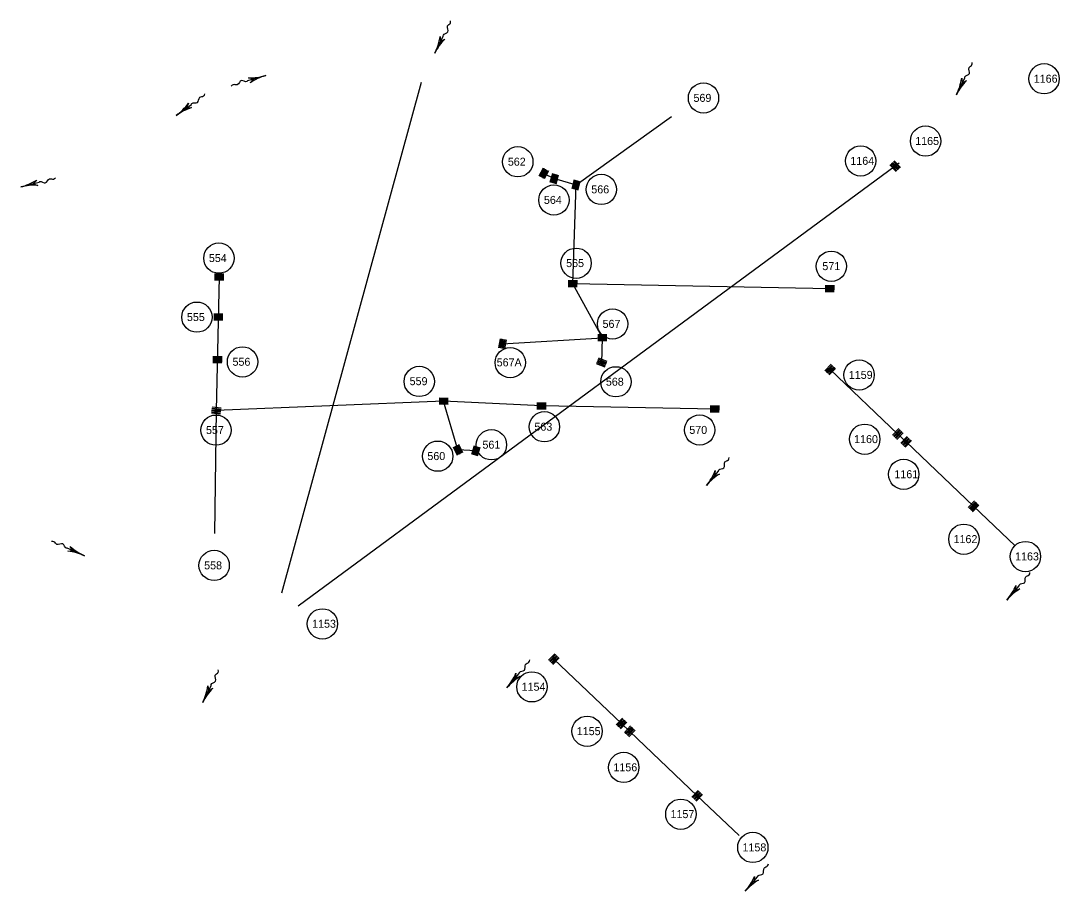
# Model space of a CAD drawing. Extents: x 594534 to 598564, y 225861 to 236229.
# Drawn here: x 596065 to 596844, y 230686 to 231339 of the extents above; entities that cross this region are included whole.
import ezdxf

# ---------------------------------------------------------------- set-up
doc = ezdxf.new("R2010")
doc.units = 0
for name, color, linetype in [('P_AREA', 7, 'Continuous'), ('P_DRN_Flow', 7, 'Continuous'), ('P_DRN_Inlet', 7, 'Continuous'), ('P_DRN_Pipes', 7, 'Continuous'), ('P_DRN_SS_UG', 7, 'Continuous'), ('P_DRN_Text', 7, 'Continuous')]:
    doc.layers.add(name, color=color, linetype=linetype)

msp = doc.modelspace()

# ---------------------------------------------------------------- linework, layer by layer
at = {"layer": 'P_AREA'}
msp.add_line((596212.74, 231083.95), (596212.76, 231084.95), dxfattribs=at)
at = {"layer": 'P_DRN_Flow'}
for p, q in [((596375.65, 231314.78), (596382.04, 231327.39)), ((596249, 231297.91), (596235.45, 231293.92)), ((596249, 231297.91), (596235.45, 231293.92)), ((596766.56, 231283.57), (596772.94, 231296.17)), ((596181.86, 231267.94), (596193.27, 231276.28)), ((596181.86, 231267.94), (596193.27, 231276.28)), ((596065.42, 231214.43), (596079.12, 231217.86)), ((596579.21, 230990.57), (596588.28, 231001.4)), ((596113.24, 230937.89), (596100.31, 230943.58)), ((596113.24, 230937.89), (596100.31, 230943.58)), ((596804.34, 230904.63), (596813.56, 230915.33)), ((596429.76, 230838.79), (596438.83, 230849.62)), ((596201.78, 230827.89), (596208.04, 230840.55)), ((596608.39, 230686.29), (596617.61, 230696.99))]:
    msp.add_line(p, q, dxfattribs=at)
for points in [[(596379.65, 231327.1), (596379.99, 231323.34), (596383.22, 231325.3)], [(596237.3, 231292.37), (596239.8, 231295.19), (596236.16, 231296.21)], [(596237.3, 231292.37), (596239.8, 231295.19), (596236.16, 231296.21)], [(596770.55, 231295.89), (596770.89, 231292.13), (596774.12, 231294.09)], [(596191.01, 231277.11), (596189.61, 231273.6), (596193.37, 231273.88)], [(596191.01, 231277.11), (596189.61, 231273.6), (596193.37, 231273.88)], [(596077.35, 231219.48), (596074.73, 231216.77), (596078.32, 231215.6)], [(596585.89, 231001.67), (596585.37, 230997.93), (596588.96, 230999.1)], [(596100.72, 230941.21), (596104.46, 230941.75), (596102.33, 230944.88)], [(596100.72, 230941.21), (596104.46, 230941.75), (596102.33, 230944.88)], [(596811.17, 230915.63), (596810.6, 230911.9), (596814.21, 230913.02)], [(596436.44, 230849.88), (596435.92, 230846.15), (596439.51, 230847.32)], [(596205.65, 230840.24), (596206.03, 230836.49), (596209.24, 230838.47)], [(596615.22, 230697.29), (596614.65, 230693.56), (596618.26, 230694.68)]]:
    msp.add_lwpolyline(points, dxfattribs=at)
for centre, start, end in [((596338.22, 231333.75), 333.12797, 350.89029), ((596413.08, 231295.82), 135.36565, 153.12797), ((596237.14, 231338.15), 268.66582, 286.42814), ((596237.14, 231338.15), 268.66582, 286.42814), ((596260.87, 231257.67), 106.42814, 124.19046), ((596260.87, 231257.67), 106.42814, 124.19046), ((596729.13, 231302.54), 333.12797, 350.89029), ((596803.98, 231264.61), 135.36565, 153.12797), ((596157.11, 231301.83), 306.14258, 323.9049), ((596157.11, 231301.83), 306.14258, 323.9049), ((596206.61, 231234.06), 108.38026, 126.14258), ((596206.61, 231234.06), 108.38026, 126.14258), ((596055.22, 231255.13), 284.06213, 301.82445), ((596075.61, 231173.73), 86.29981, 104.06213), ((596547.05, 231017.52), 320.04245, 337.80477), ((596611.37, 230963.63), 122.28013, 140.04245), ((596130.16, 230976.28), 228.45383, 246.21615), ((596130.16, 230976.28), 228.45383, 246.21615), ((596096.32, 230899.49), 66.21615, 83.97847), ((596096.32, 230899.49), 66.21615, 83.97847), ((596772.55, 230932), 319.27709, 337.03941), ((596836.14, 230877.25), 121.51478, 139.27709), ((596397.6, 230865.73), 320.04245, 337.80477), ((596461.92, 230811.84), 122.28013, 140.04245), ((596164.17, 230846.48), 333.6884, 351.45072), ((596239.39, 230809.29), 135.92608, 153.6884), ((596576.6, 230713.66), 319.27709, 337.03941), ((596640.19, 230658.91), 121.51478, 139.27709)]:
    msp.add_arc(centre, 41.96, start, end, dxfattribs=at)
for points in [[(596382.04, 231327.39), (596382.11, 231328.23), (596385.42, 231330.6), (596385.24, 231335.09), (596387.35, 231337.19), (596387.57, 231339.01)], [(596772.94, 231296.17), (596773.02, 231297.02), (596776.33, 231299.39), (596776.14, 231303.88), (596778.26, 231305.97), (596778.48, 231307.8)], [(596235.45, 231293.92), (596234.79, 231293.39), (596230.79, 231294.18), (596227.65, 231290.96), (596224.67, 231291.06), (596223.19, 231289.97)], [(596235.45, 231293.92), (596234.79, 231293.39), (596230.79, 231294.18), (596227.65, 231290.96), (596224.67, 231291.06), (596223.19, 231289.97)], [(596193.27, 231276.28), (596193.72, 231276.99), (596197.74, 231277.6), (596199.62, 231281.69), (596202.45, 231282.6), (596203.48, 231284.12)], [(596193.27, 231276.28), (596193.72, 231276.99), (596197.74, 231277.6), (596199.62, 231281.69), (596202.45, 231282.6), (596203.48, 231284.12)], [(596079.12, 231217.86), (596079.81, 231218.36), (596083.77, 231217.41), (596087.04, 231220.5), (596090.01, 231220.27), (596091.53, 231221.3)], [(596588.28, 231001.4), (596588.55, 231002.21), (596592.31, 231003.77), (596593.14, 231008.18), (596595.68, 231009.75), (596596.31, 231011.47)], [(596100.31, 230943.58), (596099.47, 230943.61), (596096.92, 230946.79), (596092.45, 230946.36), (596090.24, 230948.37), (596088.41, 230948.49)], [(596100.31, 230943.58), (596099.47, 230943.61), (596096.92, 230946.79), (596092.45, 230946.36), (596090.24, 230948.37), (596088.41, 230948.49)], [(596813.56, 230915.33), (596813.84, 230916.13), (596817.62, 230917.64), (596818.51, 230922.05), (596821.07, 230923.58), (596821.72, 230925.29)], [(596438.83, 230849.62), (596439.09, 230850.42), (596442.86, 230851.98), (596443.69, 230856.4), (596446.23, 230857.96), (596446.86, 230859.69)], [(596208.04, 230840.55), (596208.11, 230841.39), (596211.39, 230843.79), (596211.16, 230848.29), (596213.26, 230850.4), (596213.46, 230852.23)], [(596617.61, 230696.99), (596617.89, 230697.79), (596621.67, 230699.3), (596622.56, 230703.71), (596625.12, 230705.24), (596625.77, 230706.95)]]:
    msp.add_spline(points, degree=3, dxfattribs=at)
at = {"layer": 'P_DRN_Inlet'}
for p, q in [((596722.71, 231227.14), (596718.02, 231232.17)), ((596723.37, 231227.76), (596718.68, 231232.78)), ((596724.03, 231228.37), (596719.33, 231233.4)), ((596724.69, 231228.99), (596719.99, 231234.01)), ((596456.84, 231228.55), (596453.6, 231222.49)), ((596457.64, 231228.13), (596454.39, 231222.06)), ((596458.43, 231227.7), (596455.19, 231221.64)), ((596459.22, 231227.28), (596455.98, 231221.21)), ((596460.02, 231226.85), (596456.77, 231220.79)), ((596460.81, 231226.43), (596457.57, 231220.36)), ((596462.25, 231218), (596464.09, 231224.63)), ((596463.12, 231217.76), (596464.96, 231224.38)), ((596721.4, 231225.91), (596716.7, 231230.94)), ((596722.06, 231226.53), (596717.36, 231231.55)), ((596463.98, 231217.52), (596465.83, 231224.14)), ((596464.85, 231217.28), (596466.69, 231223.9)), ((596465.72, 231217.04), (596467.56, 231223.66)), ((596466.59, 231216.8), (596468.43, 231223.42)), ((596478.58, 231213.26), (596480.42, 231219.89)), ((596479.44, 231213.02), (596481.28, 231219.65)), ((596480.31, 231212.78), (596482.15, 231219.4)), ((596481.18, 231212.54), (596483.02, 231219.16)), ((596482.04, 231212.3), (596483.89, 231218.92)), ((596482.91, 231212.06), (596484.75, 231218.68)), ((596210.66, 231146.53), (596217.53, 231146.44)), ((596210.67, 231147.43), (596217.55, 231147.34)), ((596210.68, 231148.33), (596217.56, 231148.24)), ((596210.69, 231149.23), (596217.57, 231149.14)), ((596210.64, 231144.73), (596217.51, 231144.64)), ((596210.65, 231145.63), (596217.52, 231145.54)), ((596482.5, 231140.4), (596475.62, 231140.45)), ((596482.49, 231139.5), (596475.62, 231139.55)), ((596482.5, 231141.3), (596475.63, 231141.35)), ((596482.52, 231143.1), (596475.64, 231143.15)), ((596482.51, 231142.2), (596475.64, 231142.25)), ((596482.52, 231144), (596475.65, 231144.05)), ((596675.12, 231139.36), (596668.24, 231139.4)), ((596675.13, 231140.26), (596668.25, 231140.3)), ((596675.09, 231135.76), (596668.22, 231135.8)), ((596675.11, 231137.56), (596668.23, 231137.6)), ((596675.1, 231136.66), (596668.23, 231136.7)), ((596675.11, 231138.46), (596668.24, 231138.5)), ((596210.02, 231115.63), (596216.89, 231115.54)), ((596210.03, 231116.53), (596216.91, 231116.44)), ((596210.04, 231117.43), (596216.92, 231117.34)), ((596210.05, 231118.33), (596216.93, 231118.24)), ((596210.07, 231119.23), (596216.94, 231119.14)), ((596210.01, 231114.73), (596216.88, 231114.64)), ((596424.68, 231100.57), (596423.49, 231093.8)), ((596425.57, 231100.41), (596424.37, 231093.64)), ((596426.45, 231100.26), (596425.26, 231093.49)), ((596427.34, 231100.1), (596426.15, 231093.33)), ((596428.23, 231099.95), (596427.03, 231093.17)), ((596504.71, 231103.58), (596497.83, 231103.58)), ((596504.71, 231102.68), (596497.83, 231102.68)), ((596504.71, 231101.78), (596497.83, 231101.78)), ((596504.71, 231100.88), (596497.83, 231100.88)), ((596504.71, 231099.98), (596497.83, 231099.98)), ((596429.11, 231099.79), (596427.92, 231093.02)), ((596504.71, 231099.08), (596497.83, 231099.08)), ((596209.36, 231084.54), (596216.24, 231084.45)), ((596209.37, 231085.44), (596216.25, 231085.35)), ((596209.39, 231086.34), (596216.26, 231086.25)), ((596209.4, 231087.24), (596216.27, 231087.15)), ((596504.26, 231081.76), (596497.89, 231084.34)), ((596504.6, 231082.6), (596498.22, 231085.17)), ((596504.94, 231083.43), (596498.56, 231086)), ((596209.34, 231082.74), (596216.21, 231082.65)), ((596209.35, 231083.64), (596216.23, 231083.55)), ((596503.25, 231079.26), (596496.88, 231081.83)), ((596503.59, 231080.09), (596497.21, 231082.67)), ((596503.93, 231080.93), (596497.55, 231083.5)), ((596668.02, 231076.52), (596672.79, 231081.47)), ((596668.67, 231075.9), (596673.44, 231080.85)), ((596669.32, 231075.27), (596674.09, 231080.22)), ((596669.97, 231074.65), (596674.74, 231079.6)), ((596670.62, 231074.02), (596675.39, 231078.97)), ((596671.27, 231073.4), (596676.03, 231078.35)), ((596385.75, 231053.17), (596378.88, 231053.22)), ((596385.77, 231054.97), (596378.89, 231055.02)), ((596385.76, 231054.07), (596378.89, 231054.12)), ((596385.77, 231055.87), (596378.9, 231055.92)), ((596208.37, 231045.84), (596215.2, 231045.07)), ((596208.47, 231046.74), (596215.31, 231045.96)), ((596208.58, 231047.63), (596215.41, 231046.86)), ((596208.68, 231048.53), (596215.51, 231047.75)), ((596208.78, 231049.42), (596215.61, 231048.65)), ((596385.75, 231052.27), (596378.87, 231052.32)), ((596385.74, 231051.37), (596378.87, 231051.42)), ((596452.21, 231052.46), (596459.08, 231052.46)), ((596452.21, 231051.56), (596459.08, 231051.56)), ((596452.21, 231050.66), (596459.08, 231050.66)), ((596452.21, 231049.76), (596459.08, 231049.76)), ((596452.21, 231048.86), (596459.08, 231048.86)), ((596452.21, 231047.96), (596459.08, 231047.96)), ((596588.91, 231045.41), (596582.04, 231045.46)), ((596588.93, 231047.21), (596582.05, 231047.26)), ((596588.92, 231046.31), (596582.05, 231046.36)), ((596588.94, 231049.01), (596582.06, 231049.06)), ((596588.93, 231048.11), (596582.06, 231048.16)), ((596588.95, 231049.91), (596582.07, 231049.96)), ((596208.27, 231044.95), (596215.1, 231044.18)), ((596718.68, 231028.18), (596723.42, 231033.16)), ((596719.33, 231027.56), (596724.07, 231032.54)), ((596719.98, 231026.94), (596724.73, 231031.92)), ((596720.63, 231026.32), (596725.38, 231031.3)), ((596721.28, 231025.7), (596726.03, 231030.67)), ((596721.94, 231025.08), (596726.68, 231030.05)), ((596724.83, 231022.32), (596729.57, 231027.29)), ((596725.48, 231021.69), (596730.22, 231026.67)), ((596726.13, 231021.07), (596730.88, 231026.05)), ((596726.78, 231020.45), (596731.53, 231025.43)), ((596727.44, 231019.83), (596732.18, 231024.81)), ((596728.09, 231019.21), (596732.83, 231024.19)), ((596389.42, 231019.45), (596392.5, 231013.31)), ((596390.22, 231019.86), (596393.3, 231013.71)), ((596391.03, 231020.26), (596394.11, 231014.11)), ((596391.83, 231020.66), (596394.91, 231014.51)), ((596392.64, 231021.07), (596395.71, 231014.92)), ((596393.44, 231021.47), (596396.52, 231015.32)), ((596403.35, 231013.96), (596405.34, 231020.54)), ((596404.21, 231013.7), (596406.2, 231020.28)), ((596405.07, 231013.44), (596407.06, 231020.02)), ((596405.94, 231013.18), (596407.92, 231019.76)), ((596406.8, 231012.92), (596408.79, 231019.5)), ((596407.66, 231012.66), (596409.65, 231019.24)), ((596775.48, 230974), (596780.22, 230978.97)), ((596776.13, 230973.38), (596780.87, 230978.35)), ((596776.78, 230972.76), (596781.53, 230977.73)), ((596777.43, 230972.14), (596782.18, 230977.11)), ((596778.09, 230971.51), (596782.83, 230976.49)), ((596778.74, 230970.89), (596783.48, 230975.87)), ((596460.95, 230859.45), (596465.72, 230864.4)), ((596461.6, 230858.82), (596466.37, 230863.78)), ((596462.25, 230858.2), (596467.02, 230863.15)), ((596462.9, 230857.57), (596467.66, 230862.53)), ((596463.54, 230856.95), (596468.31, 230861.9)), ((596464.19, 230856.33), (596468.96, 230861.28)), ((596511.61, 230811.08), (596516.32, 230816.09)), ((596512.27, 230810.46), (596516.97, 230815.48)), ((596512.92, 230809.85), (596517.63, 230814.86)), ((596513.58, 230809.23), (596518.29, 230814.24)), ((596514.24, 230808.62), (596518.94, 230813.63)), ((596514.89, 230808), (596519.6, 230813.01)), ((596517.76, 230805.21), (596522.47, 230810.22)), ((596518.42, 230804.6), (596523.13, 230809.61)), ((596519.07, 230803.98), (596523.78, 230808.99)), ((596519.73, 230803.36), (596524.44, 230808.38)), ((596520.39, 230802.75), (596525.09, 230807.76)), ((596521.04, 230802.13), (596525.75, 230807.14)), ((596568.41, 230756.93), (596573.15, 230761.9)), ((596569.06, 230756.3), (596573.8, 230761.28)), ((596569.71, 230755.68), (596574.45, 230760.66)), ((596570.36, 230755.06), (596575.1, 230760.04)), ((596571.01, 230754.44), (596575.76, 230759.42)), ((596571.66, 230753.82), (596576.41, 230758.8))]:
    msp.add_line(p, q, dxfattribs=at)
for points in [[(596456.79, 231225.81), (596455.85, 231224.05), (596457.62, 231223.1), (596458.56, 231224.87)], [(596722.11, 231229.92), (596720.74, 231231.38), (596719.28, 231230.01), (596720.65, 231228.55)], [(596466.03, 231219.48), (596466.57, 231221.41), (596464.64, 231221.94), (596464.11, 231220.02)], [(596482.36, 231214.74), (596482.9, 231216.67), (596480.97, 231217.2), (596480.43, 231215.28)], [(596213.09, 231145.94), (596215.09, 231145.92), (596215.11, 231147.92), (596213.11, 231147.94)], [(596480.08, 231142.77), (596478.08, 231142.78), (596478.06, 231140.78), (596480.06, 231140.77)], [(596672.68, 231139.02), (596670.68, 231139.04), (596670.67, 231137.04), (596672.67, 231137.02)], [(596212.46, 231115.95), (596214.46, 231115.92), (596214.49, 231117.92), (596212.49, 231117.95)], [(596502.27, 231102.33), (596500.27, 231102.33), (596500.27, 231100.33), (596502.27, 231100.33)], [(596425.49, 231097.95), (596425.14, 231095.98), (596427.11, 231095.64), (596427.46, 231097.61)], [(596211.79, 231083.96), (596213.79, 231083.93), (596213.82, 231085.93), (596211.82, 231085.96)], [(596502.21, 231083.18), (596500.35, 231083.93), (596499.6, 231082.08), (596501.46, 231081.33)], [(596672.06, 231076.02), (596673.44, 231077.46), (596672, 231078.85), (596670.62, 231077.41)], [(596383.33, 231054.63), (596381.33, 231054.65), (596381.31, 231052.65), (596383.31, 231052.63)], [(596210.83, 231045.92), (596212.82, 231045.69), (596213.05, 231047.68), (596211.06, 231047.9)], [(596454.65, 231049.21), (596456.65, 231049.21), (596456.65, 231051.21), (596454.65, 231051.21)], [(596586.5, 231048.68), (596584.5, 231048.7), (596584.49, 231046.7), (596586.49, 231046.68)], [(596722.71, 231027.7), (596724.09, 231029.15), (596722.65, 231030.53), (596721.27, 231029.08)], [(596728.86, 231021.84), (596730.24, 231023.28), (596728.8, 231024.66), (596727.42, 231023.22)], [(596391.63, 231017.83), (596392.52, 231016.05), (596394.31, 231016.94), (596393.42, 231018.73)], [(596407.17, 231015.35), (596407.75, 231017.27), (596405.83, 231017.85), (596405.25, 231015.93)], [(596779.51, 230973.52), (596780.89, 230974.97), (596779.45, 230976.35), (596778.07, 230974.9)], [(596464.98, 230858.95), (596466.37, 230860.39), (596464.93, 230861.78), (596463.54, 230860.34)], [(596515.65, 230810.63), (596517.02, 230812.09), (596515.56, 230813.46), (596514.19, 230812)], [(596521.8, 230804.77), (596523.17, 230806.22), (596521.71, 230807.59), (596520.34, 230806.13)], [(596572.44, 230756.45), (596573.82, 230757.9), (596572.37, 230759.28), (596570.99, 230757.83)]]:
    msp.add_lwpolyline(points, close=True, dxfattribs=at)
at = {"layer": 'P_DRN_Pipes'}
msp.add_line((596365.41, 231292.62), (596260.82, 230909.73), dxfattribs=at)
at = {"layer": 'P_DRN_SS_UG'}
for p, q in [((596481.66, 231215.97), (596553.05, 231267.32)), ((596723.67, 231232.21), (596720.69, 231229.96)), ((596720.69, 231229.96), (596273.27, 230900.09)), ((596457.21, 231224.46), (596465.34, 231220.71)), ((596465.34, 231220.71), (596481.66, 231215.97)), ((596479.07, 231141.78), (596481.66, 231215.97)), ((596214.1, 231146.93), (596211.94, 231046.81)), ((596501.27, 231101.33), (596479.07, 231141.78)), ((596671.67, 231138.03), (596479.07, 231141.78)), ((596426.3, 231096.79), (596501.27, 231101.33)), ((596500.91, 231082.63), (596501.27, 231101.33)), ((596672.03, 231077.44), (596722.68, 231029.12)), ((596382.32, 231053.64), (596211.94, 231046.8)), ((596455.65, 231050.21), (596382.32, 231053.64)), ((596392.97, 231017.39), (596382.32, 231053.64)), ((596211.94, 231046.81), (596210.65, 230954.48)), ((596585.49, 231047.69), (596455.65, 231050.21)), ((596722.68, 231029.12), (596728.83, 231023.25)), ((596728.83, 231023.25), (596779.48, 230974.93)), ((596406.5, 231016.6), (596392.97, 231017.39)), ((596779.48, 230974.93), (596810.5, 230945.35)), ((596464.96, 230860.36), (596515.61, 230812.05)), ((596515.61, 230812.05), (596521.76, 230806.18)), ((596521.76, 230806.18), (596572.41, 230757.86)), ((596572.41, 230757.86), (596603.66, 230728.05))]:
    msp.add_line(p, q, dxfattribs=at)
at = {"layer": 'P_DRN_Text'}
for centre in [(596832.28, 231295.48), (596577.05, 231281.11), (596743.46, 231248.78), (596437.91, 231233.25), (596694.84, 231233.89), (596500.48, 231212.51), (596464.96, 231204.59), (596213.88, 231161.01), (596481.61, 231157.22), (596672.86, 231154.94), (596197.43, 231116.76), (596508.92, 231111.63), (596231.59, 231083.22), (596432.24, 231082.64), (596693.68, 231073.39), (596364.04, 231068.53), (596511.39, 231068.27), (596457.84, 231034.54), (596211.74, 231032.03), (596574.18, 231032.14), (596418.14, 231021.05), (596697.93, 231025.23), (596377.89, 231012.52), (596727.09, 230998.91), (596772.19, 230950.25), (596818.32, 230937.27), (596210.34, 230930.59), (596291.5, 230886.78), (596448.48, 230839.55), (596489.84, 230806.25), (596517.28, 230779.14), (596560.08, 230744.04), (596614.02, 230719.1)]:
    msp.add_circle(centre, 11.36, dxfattribs=at)

# ---------------------------------------------------------------- texts
for s, p in [('1166', (596824.55, 231292.56)), ('569', (596569.56, 231278.19)), ('1165', (596735.72, 231245.86)), ('562', (596430.42, 231230.33)), ('1164', (596687.11, 231230.97)), ('566', (596492.98, 231209.59)), ('564', (596457.47, 231201.67)), ('554', (596206.38, 231158.09)), ('565', (596474.12, 231154.3)), ('571', (596666.12, 231152.02)), ('555', (596189.93, 231113.84)), ('567', (596501.42, 231108.71)), ('556', (596224.09, 231080.3)), ('567A', (596422.08, 231079.86)), ('1159', (596685.94, 231070.47)), ('559', (596356.83, 231065.75)), ('568', (596503.89, 231065.35)), ('563', (596450.35, 231031.62)), ('557', (596204.24, 231029.11)), ('570', (596566.42, 231029.22)), ('561', (596411.4, 231018.13)), ('1160', (596689.93, 231022.31)), ('560', (596370.13, 231009.6)), ('1161', (596720.11, 230995.99)), ('1162', (596764.45, 230947.33)), ('1163', (596810.58, 230934.35)), ('558', (596202.84, 230927.67)), ('1153', (596283.77, 230883.86)), ('1154', (596440.75, 230836.63)), ('1155', (596482.1, 230803.33)), ('1156', (596509.54, 230776.22)), ('1157', (596552.34, 230741.13)), ('1158', (596606.28, 230716.18))]:
    msp.add_text(s, height=6, dxfattribs=at).set_placement(p)

doc.saveas('drawing.dxf')
